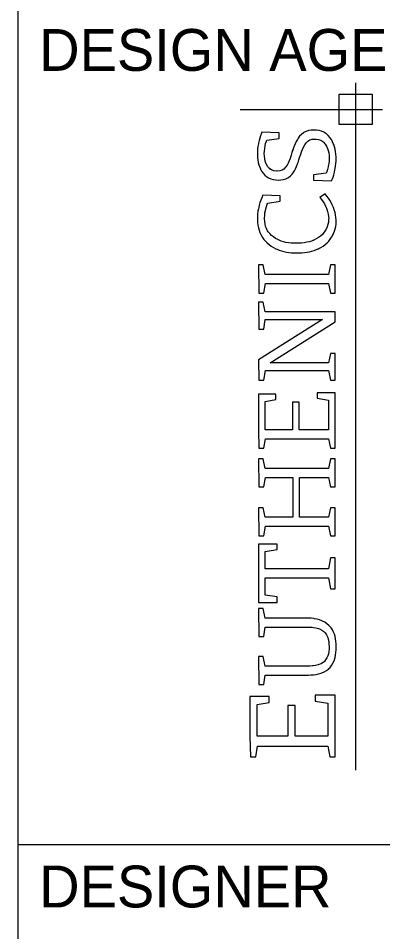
# Model space of a CAD drawing. Extents: x 0 to 34, y 0 to 22.
# Drawn here: x 32 to 32.871, y 2.292 to 4.476 of the extents above; entities that cross this region are included whole.
import ezdxf

# ---------------------------------------------------------------- set-up
doc = ezdxf.new("R2010")
doc.units = 0
for name, color, linetype in [('SH_Border', 7, 'Continuous'), ('SH_Data', 7, 'Continuous'), ('SH_Logo', 7, 'Continuous')]:
    doc.layers.add(name, color=color, linetype=linetype)

msp = doc.modelspace()

# ---------------------------------------------------------------- linework, layer by layer
at = {"layer": 'SH_Border'}
for p, q in [((32, 0.5), (32, 21.5)), ((32, 2.5), (33.5, 2.5))]:
    msp.add_line(p, q, dxfattribs=at)
at = {"layer": 'SH_Data'}
msp.add_line((32.75, 3.5), (32.75, 3.5), dxfattribs=at)
at = {"layer": 'SH_Logo'}
for p, q in [((32.8065, 2.6784), (32.8065, 4.3216)), ((32.5305, 4.258), (32.8702, 4.258))]:
    msp.add_line(p, q, dxfattribs=at)
for points in [[(32.767, 4.2214), (32.767, 4.2945), (32.846, 4.2945), (32.846, 4.2214)], [(32.6388, 4.1194), (32.6348, 4.1153), (32.6304, 4.1125), (32.6249, 4.1107), (32.6175, 4.11), (32.6107, 4.1109), (32.6052, 4.113), (32.6005, 4.1162), (32.5964, 4.1207), (32.5933, 4.1258), (32.5908, 4.1316), (32.5902, 4.134), (32.5889, 4.1399), (32.5882, 4.1459), (32.5879, 4.1522), (32.5882, 4.1584), (32.5888, 4.1644), (32.5898, 4.1705), (32.5911, 4.1762), (32.5929, 4.1821), (32.594, 4.1847), (32.6234, 4.1884), (32.6234, 4.2015), (32.5822, 4.2037), (32.581, 4.2007), (32.5788, 4.1949), (32.5769, 4.1891), (32.5753, 4.1833), (32.574, 4.1774), (32.5737, 4.1758), (32.5727, 4.1695), (32.572, 4.1635), (32.5715, 4.1574), (32.5714, 4.1516), (32.5714, 4.1494), (32.5718, 4.143), (32.5724, 4.1369), (32.5736, 4.1309), (32.575, 4.1252), (32.5769, 4.1198), (32.5787, 4.1156), (32.5816, 4.1102), (32.5851, 4.1052), (32.589, 4.101), (32.5935, 4.0973), (32.5981, 4.0942), (32.6033, 4.0919), (32.609, 4.0902), (32.6151, 4.0891), (32.6216, 4.0888), (32.6275, 4.0891), (32.6336, 4.0901), (32.6391, 4.0919), (32.644, 4.0943), (32.6458, 4.0954), (32.6506, 4.0991), (32.6548, 4.1034), (32.6584, 4.1083), (32.6599, 4.1107), (32.6627, 4.116), (32.6652, 4.1216), (32.6674, 4.1274), (32.6686, 4.131), (32.6706, 4.1369), (32.6724, 4.1426), (32.6742, 4.1485), (32.6749, 4.1508), (32.6769, 4.1567), (32.6791, 4.1623), (32.6816, 4.1676), (32.6844, 4.1728), (32.688, 4.1777), (32.6921, 4.1818), (32.6922, 4.1819), (32.697, 4.1848), (32.7026, 4.1865), (32.7092, 4.1871), (32.7115, 4.187), (32.7177, 4.186), (32.7231, 4.184), (32.7278, 4.1808), (32.7294, 4.1793), (32.7333, 4.175), (32.7366, 4.17), (32.7391, 4.1642), (32.7406, 4.1598), (32.742, 4.154), (32.7428, 4.1479), (32.7431, 4.141), (32.7428, 4.1344), (32.7421, 4.1283), (32.7409, 4.1222), (32.7406, 4.1203), (32.739, 4.1144), (32.737, 4.1086), (32.7355, 4.1052), (32.7054, 4.1011), (32.7054, 4.0883), (32.7486, 4.0867), (32.75, 4.0901), (32.7521, 4.0959), (32.7539, 4.1017), (32.7555, 4.1076), (32.7567, 4.1135), (32.7573, 4.1162), (32.7583, 4.1223), (32.759, 4.1283), (32.7595, 4.1343), (32.7596, 4.1403), (32.7596, 4.1447), (32.7591, 4.151), (32.7583, 4.1571), (32.7572, 4.1629), (32.7557, 4.1687), (32.7536, 4.1749), (32.7512, 4.1806), (32.7482, 4.1859), (32.7448, 4.1908), (32.7409, 4.1952), (32.7365, 4.1992), (32.7349, 4.2004), (32.7301, 4.2033), (32.7248, 4.2055), (32.719, 4.2071), (32.7129, 4.2081), (32.7063, 4.2084), (32.7, 4.2081), (32.6939, 4.2071), (32.6883, 4.2054), (32.6834, 4.2031), (32.6814, 4.2018), (32.6766, 4.198), (32.6723, 4.1938), (32.6687, 4.1889), (32.6671, 4.1863), (32.6642, 4.1811), (32.6616, 4.1755), (32.6592, 4.1698), (32.6579, 4.1661), (32.6541, 4.1546), (32.6524, 4.1487), (32.6497, 4.1405), (32.6474, 4.1349), (32.645, 4.1296), (32.6423, 4.1243)], [(32.7054, 4.1011), (32.7054, 4.0883), (32.7486, 4.0867), (32.75, 4.0901), (32.7521, 4.0959), (32.7539, 4.1017), (32.7555, 4.1076), (32.7567, 4.1135), (32.7573, 4.1162), (32.7583, 4.1223), (32.759, 4.1283), (32.7595, 4.1343), (32.7596, 4.1403), (32.7596, 4.1447), (32.7591, 4.151), (32.7583, 4.1571), (32.7572, 4.1629), (32.7557, 4.1687), (32.7539, 4.1742), (32.7536, 4.1749), (32.7512, 4.1806), (32.7482, 4.1859), (32.7448, 4.1908), (32.7409, 4.1952), (32.7365, 4.1992), (32.7349, 4.2004), (32.7301, 4.2033), (32.7248, 4.2055), (32.719, 4.2071), (32.7129, 4.2081), (32.7063, 4.2084), (32.7, 4.2081), (32.6939, 4.2071), (32.6883, 4.2054), (32.6834, 4.2031), (32.6814, 4.2018), (32.6766, 4.198), (32.6723, 4.1938), (32.6687, 4.1889), (32.6671, 4.1863), (32.6642, 4.1811), (32.6616, 4.1755), (32.6592, 4.1698), (32.6579, 4.1661), (32.656, 4.1603), (32.6541, 4.1546), (32.6524, 4.1487), (32.6516, 4.1464), (32.6497, 4.1405), (32.6474, 4.1349), (32.645, 4.1296), (32.6423, 4.1243), (32.6388, 4.1194), (32.6348, 4.1153), (32.6304, 4.1125), (32.6249, 4.1107), (32.6184, 4.1101), (32.6169, 4.1101), (32.6107, 4.1109), (32.6052, 4.113), (32.6006, 4.1161), (32.6003, 4.1164), (32.5964, 4.1207), (32.5933, 4.1258), (32.5908, 4.1316), (32.5902, 4.134), (32.5889, 4.1399), (32.5882, 4.1459), (32.5879, 4.1521), (32.5879, 4.1524), (32.5882, 4.1584), (32.5888, 4.1644), (32.5898, 4.1705), (32.5911, 4.1762), (32.5929, 4.1821), (32.594, 4.1847), (32.6234, 4.1884), (32.6234, 4.2015), (32.5822, 4.2037), (32.581, 4.2007), (32.5788, 4.1949), (32.5769, 4.1891), (32.5753, 4.1833), (32.574, 4.1774), (32.5737, 4.1758), (32.5727, 4.1695), (32.572, 4.1635), (32.5715, 4.1574), (32.5714, 4.1516), (32.5714, 4.1494), (32.5718, 4.143), (32.5724, 4.1369), (32.5736, 4.1309), (32.575, 4.1252), (32.5769, 4.1198), (32.5787, 4.1156), (32.5816, 4.1102), (32.5851, 4.1052), (32.589, 4.101), (32.5935, 4.0973), (32.5981, 4.0942), (32.6033, 4.0919), (32.609, 4.0902), (32.6151, 4.0891), (32.6216, 4.0888), (32.6275, 4.0891), (32.6336, 4.0901), (32.6391, 4.0919), (32.644, 4.0943), (32.6458, 4.0954), (32.6506, 4.0991), (32.6548, 4.1034), (32.6584, 4.1083), (32.6599, 4.1107), (32.6627, 4.116), (32.6652, 4.1216), (32.6674, 4.1274), (32.6686, 4.131), (32.6706, 4.1369), (32.6724, 4.1426), (32.6742, 4.1485), (32.6749, 4.1508), (32.6769, 4.1567), (32.6791, 4.1623), (32.6816, 4.1676), (32.6844, 4.1728), (32.688, 4.1777), (32.6921, 4.1818), (32.6922, 4.1819), (32.697, 4.1848), (32.7026, 4.1865), (32.7092, 4.1871), (32.7115, 4.187), (32.7177, 4.186), (32.7231, 4.184), (32.7278, 4.1808), (32.7294, 4.1793), (32.7333, 4.175), (32.7366, 4.17), (32.7391, 4.1642), (32.7406, 4.1598), (32.742, 4.154), (32.7428, 4.1479), (32.7431, 4.1416), (32.7431, 4.1403), (32.7428, 4.1344), (32.7421, 4.1283), (32.7409, 4.1222), (32.7406, 4.1203), (32.739, 4.1144), (32.737, 4.1086), (32.7355, 4.1052)], [(32.587, 3.9472), (32.5908, 3.9428), (32.5949, 3.9386), (32.5995, 3.9347), (32.6044, 3.9311), (32.6097, 3.9279), (32.6153, 3.9249), (32.6186, 3.9234), (32.6237, 3.9213), (32.6291, 3.9196), (32.6348, 3.9181), (32.6406, 3.9168), (32.6467, 3.9158), (32.653, 3.9152), (32.6595, 3.9148), (32.6663, 3.9146), (32.6709, 3.9147), (32.6776, 3.915), (32.684, 3.9156), (32.6902, 3.9165), (32.6961, 3.9176), (32.7018, 3.919), (32.7072, 3.9207), (32.7124, 3.9226), (32.7173, 3.9249), (32.7174, 3.9249), (32.7231, 3.9279), (32.7284, 3.9312), (32.7333, 3.9348), (32.7378, 3.9387), (32.7419, 3.9429), (32.7456, 3.9474), (32.7488, 3.9522), (32.751, 3.9558), (32.7536, 3.9612), (32.7558, 3.9668), (32.7574, 3.9725), (32.7586, 3.9783), (32.7594, 3.9843), (32.7596, 3.9906), (32.7596, 3.9937), (32.7591, 3.9995), (32.7583, 4.0055), (32.757, 4.0114), (32.7552, 4.0174), (32.7531, 4.0234), (32.7525, 4.0248), (32.7502, 4.0301), (32.7475, 4.0354), (32.7446, 4.0406), (32.7412, 4.0457), (32.7374, 4.0507), (32.7333, 4.0557), (32.7205, 4.047), (32.7244, 4.0422), (32.7282, 4.0371), (32.7314, 4.032), (32.7342, 4.0268), (32.7365, 4.0216), (32.7372, 4.0197), (32.7392, 4.0135), (32.7406, 4.0076), (32.7415, 4.0017), (32.7418, 3.9961), (32.7417, 3.9945), (32.7412, 3.9884), (32.7401, 3.9825), (32.7382, 3.9769), (32.7357, 3.9715), (32.7326, 3.9664), (32.7304, 3.9633), (32.7266, 3.959), (32.7223, 3.9551), (32.7175, 3.9515), (32.7121, 3.9482), (32.7063, 3.9453), (32.7054, 3.945), (32.7004, 3.9431), (32.695, 3.9415), (32.6893, 3.9401), (32.6834, 3.9391), (32.6771, 3.9383), (32.6706, 3.9379), (32.6636, 3.9377), (32.6583, 3.9378), (32.6518, 3.9383), (32.6456, 3.939), (32.6396, 3.94), (32.6339, 3.9414), (32.6285, 3.9431), (32.6234, 3.9451), (32.6202, 3.9466), (32.6147, 3.9495), (32.6096, 3.9529), (32.605, 3.9567), (32.601, 3.9608), (32.5974, 3.9653), (32.5959, 3.9677), (32.5933, 3.9728), (32.5911, 3.9782), (32.5897, 3.984), (32.5888, 3.9902), (32.5885, 3.9966), (32.5885, 3.9982), (32.5888, 4.0041), (32.5895, 4.0102), (32.5906, 4.0165), (32.5914, 4.0202), (32.5931, 4.026), (32.5951, 4.0317), (32.596, 4.034), (32.6258, 4.0384), (32.6258, 4.0513), (32.5845, 4.0531), (32.5843, 4.0525), (32.5818, 4.0466), (32.5795, 4.0407), (32.5776, 4.0349), (32.5759, 4.0292), (32.5746, 4.0237), (32.5739, 4.0204), (32.5727, 4.0143), (32.572, 4.0082), (32.5715, 4.0022), (32.5714, 3.9963), (32.5715, 3.9934), (32.5718, 3.9871), (32.5726, 3.981), (32.5738, 3.9751), (32.5754, 3.9694), (32.5775, 3.9638), (32.5799, 3.9586), (32.5827, 3.9535), (32.5836, 3.952)], [(32.6518, 3.9383), (32.6456, 3.939), (32.6396, 3.94), (32.6339, 3.9414), (32.6285, 3.9431), (32.6234, 3.9451), (32.6202, 3.9466), (32.6147, 3.9495), (32.6096, 3.9529), (32.605, 3.9567), (32.601, 3.9608), (32.5974, 3.9653), (32.5959, 3.9677), (32.5933, 3.9728), (32.5911, 3.9782), (32.5897, 3.984), (32.5888, 3.9902), (32.5885, 3.9966), (32.5885, 3.9982), (32.5888, 4.0041), (32.5895, 4.0102), (32.5906, 4.0165), (32.5914, 4.0202), (32.5931, 4.026), (32.5951, 4.0317), (32.596, 4.034), (32.6258, 4.0384), (32.6258, 4.0513), (32.5846, 4.0531), (32.5818, 4.0466), (32.5795, 4.0407), (32.5776, 4.0349), (32.5759, 4.0292), (32.5746, 4.0237), (32.5739, 4.0204), (32.5727, 4.0143), (32.572, 4.0082), (32.5715, 4.0022), (32.5714, 3.9963), (32.5715, 3.9934), (32.5718, 3.9871), (32.5726, 3.981), (32.5738, 3.9751), (32.5754, 3.9694), (32.5775, 3.9638), (32.5799, 3.9586), (32.5827, 3.9535), (32.5836, 3.952), (32.587, 3.9472), (32.5908, 3.9428), (32.5949, 3.9386), (32.5995, 3.9347), (32.6044, 3.9311), (32.6097, 3.9279), (32.6153, 3.9249), (32.6186, 3.9234), (32.6237, 3.9213), (32.6291, 3.9196), (32.6348, 3.9181), (32.6406, 3.9168), (32.6467, 3.9158), (32.653, 3.9152), (32.6595, 3.9148), (32.6663, 3.9146), (32.6709, 3.9147), (32.6776, 3.915), (32.684, 3.9156), (32.6902, 3.9165), (32.6961, 3.9176), (32.7018, 3.919), (32.7072, 3.9207), (32.7124, 3.9226), (32.7179, 3.9252), (32.7231, 3.9279), (32.7284, 3.9312), (32.7333, 3.9348), (32.7378, 3.9387), (32.7419, 3.9429), (32.7456, 3.9474), (32.7488, 3.9522), (32.751, 3.9558), (32.7536, 3.9612), (32.7558, 3.9668), (32.7574, 3.9725), (32.7586, 3.9783), (32.7594, 3.9843), (32.7596, 3.9906), (32.7596, 3.9937), (32.7591, 3.9995), (32.7583, 4.0055), (32.757, 4.0114), (32.7552, 4.0174), (32.7531, 4.0234), (32.7525, 4.0248), (32.7502, 4.0301), (32.7475, 4.0354), (32.7446, 4.0406), (32.7412, 4.0457), (32.7374, 4.0507), (32.7333, 4.0557), (32.7205, 4.047), (32.7244, 4.0422), (32.7282, 4.0371), (32.7314, 4.032), (32.7342, 4.0268), (32.7365, 4.0216), (32.7372, 4.0197), (32.7392, 4.0135), (32.7406, 4.0076), (32.7415, 4.0017), (32.7418, 3.9961), (32.7417, 3.9945), (32.7412, 3.9884), (32.7401, 3.9825), (32.7382, 3.9769), (32.7357, 3.9715), (32.7326, 3.9664), (32.7304, 3.9633), (32.7266, 3.959), (32.7223, 3.9551), (32.7175, 3.9515), (32.7121, 3.9482), (32.706, 3.9452), (32.7004, 3.9431), (32.695, 3.9415), (32.6893, 3.9401), (32.6834, 3.9391), (32.6771, 3.9383), (32.6706, 3.9379), (32.6636, 3.9377), (32.6583, 3.9378)], [(32.5737, 3.886), (32.5751, 3.8189), (32.5864, 3.8189), (32.5905, 3.8416), (32.7413, 3.8416), (32.746, 3.8189), (32.7573, 3.8189), (32.7573, 3.886), (32.746, 3.886), (32.7413, 3.8631), (32.5902, 3.8631), (32.5851, 3.886)], [(32.5902, 3.8631), (32.5851, 3.886), (32.5737, 3.886), (32.5751, 3.8189), (32.5864, 3.8189), (32.5905, 3.8416), (32.7413, 3.8416), (32.746, 3.8189), (32.7573, 3.8189), (32.7573, 3.886), (32.746, 3.886), (32.7413, 3.8631)], [(32.5904, 3.6335), (32.7412, 3.6335), (32.746, 3.6109), (32.7573, 3.6109), (32.7573, 3.6745), (32.746, 3.6745), (32.7412, 3.6519), (32.6016, 3.6519), (32.7573, 3.7496), (32.7573, 3.7738), (32.5903, 3.7738), (32.5851, 3.7967), (32.5737, 3.7967), (32.5751, 3.7328), (32.5864, 3.7328), (32.5902, 3.7556), (32.7267, 3.7556), (32.5737, 3.6593), (32.5751, 3.6109), (32.5864, 3.6109)], [(32.6016, 3.6519), (32.7573, 3.7496), (32.7573, 3.7738), (32.5903, 3.7738), (32.5851, 3.7967), (32.5737, 3.7967), (32.5751, 3.7328), (32.5864, 3.7328), (32.5902, 3.7556), (32.7267, 3.7556), (32.5737, 3.6593), (32.5751, 3.6109), (32.5864, 3.6109), (32.5904, 3.6335), (32.7412, 3.6335), (32.746, 3.6109), (32.7573, 3.6109), (32.7573, 3.6745), (32.746, 3.6745), (32.7412, 3.6519)], [(32.7142, 3.5804), (32.7142, 3.5673), (32.7412, 3.5631), (32.7412, 3.4918), (32.6713, 3.4918), (32.6713, 3.5581), (32.6555, 3.5581), (32.6555, 3.4918), (32.5898, 3.4918), (32.5898, 3.5599), (32.6153, 3.5641), (32.6153, 3.5773), (32.5737, 3.5773), (32.5737, 3.4916), (32.5751, 3.4478), (32.5864, 3.4478), (32.5905, 3.4703), (32.7412, 3.4703), (32.746, 3.4478), (32.7573, 3.4478), (32.7573, 3.5804)], [(32.6555, 3.5581), (32.6555, 3.4918), (32.5898, 3.4918), (32.5898, 3.5599), (32.6153, 3.5641), (32.6153, 3.5773), (32.5737, 3.5773), (32.5737, 3.4916), (32.5751, 3.4478), (32.5864, 3.4478), (32.5905, 3.4703), (32.7412, 3.4703), (32.746, 3.4478), (32.7573, 3.4478), (32.7573, 3.5804), (32.7142, 3.5804), (32.7142, 3.5673), (32.7412, 3.5631), (32.7412, 3.4918), (32.6713, 3.4918), (32.6713, 3.5581)], [(32.5737, 3.4222), (32.5751, 3.3553), (32.5864, 3.3553), (32.5904, 3.3778), (32.6558, 3.3778), (32.6558, 3.2828), (32.5903, 3.2828), (32.5851, 3.3056), (32.5737, 3.3056), (32.5751, 3.2386), (32.5864, 3.2386), (32.5904, 3.2612), (32.7412, 3.2612), (32.746, 3.2386), (32.7573, 3.2386), (32.7573, 3.3056), (32.746, 3.3056), (32.7412, 3.2828), (32.6719, 3.2828), (32.6719, 3.3778), (32.7412, 3.3778), (32.746, 3.3553), (32.7573, 3.3553), (32.7573, 3.4222), (32.746, 3.4222), (32.7412, 3.3994), (32.5903, 3.3994), (32.5851, 3.4222)], [(32.5903, 3.3994), (32.5851, 3.4222), (32.5737, 3.4222), (32.5751, 3.3553), (32.5864, 3.3553), (32.5904, 3.3778), (32.6558, 3.3778), (32.6558, 3.2828), (32.5903, 3.2828), (32.5851, 3.3056), (32.5737, 3.3056), (32.5751, 3.2386), (32.5864, 3.2386), (32.5904, 3.2612), (32.7412, 3.2612), (32.746, 3.2386), (32.7573, 3.2386), (32.7573, 3.3056), (32.746, 3.3056), (32.7412, 3.2828), (32.6719, 3.2828), (32.6719, 3.3778), (32.7412, 3.3778), (32.746, 3.3553), (32.7573, 3.3553), (32.7573, 3.4222), (32.746, 3.4222), (32.7412, 3.3994)], [(32.5898, 3.1595), (32.5898, 3.2008), (32.6187, 3.2055), (32.6187, 3.2186), (32.5737, 3.2186), (32.5737, 3.0791), (32.6187, 3.0791), (32.6187, 3.0922), (32.5898, 3.0968), (32.5898, 3.1382), (32.7412, 3.1382), (32.746, 3.1119), (32.7573, 3.1119), (32.7573, 3.1858), (32.746, 3.1858), (32.7412, 3.1595)], [(32.5898, 3.1595), (32.5898, 3.2008), (32.6187, 3.2055), (32.6187, 3.2186), (32.5737, 3.2186), (32.5737, 3.0791), (32.6187, 3.0791), (32.6187, 3.0922), (32.5898, 3.0968), (32.5898, 3.1382), (32.7412, 3.1382), (32.746, 3.1119), (32.7573, 3.1119), (32.7573, 3.1858), (32.746, 3.1858), (32.7412, 3.1595)], [(32.7428, 2.973), (32.7427, 2.9683), (32.7421, 2.9618), (32.741, 2.9561), (32.7394, 2.9512), (32.7376, 2.9469), (32.7345, 2.9417), (32.7307, 2.9375), (32.7292, 2.9361), (32.7242, 2.9327), (32.7186, 2.9304), (32.7164, 2.9297), (32.7105, 2.9283), (32.7045, 2.9276), (32.7029, 2.9274), (32.6967, 2.9271), (32.6908, 2.927), (32.5902, 2.927), (32.5851, 2.9498), (32.5737, 2.9498), (32.5751, 2.8829), (32.5864, 2.8829), (32.5903, 2.9054), (32.6908, 2.9054), (32.6932, 2.9055), (32.6991, 2.9057), (32.7057, 2.9063), (32.7116, 2.907), (32.7175, 2.9083), (32.7236, 2.9099), (32.7257, 2.9106), (32.7311, 2.913), (32.7363, 2.9161), (32.7412, 2.9199), (32.7413, 2.92), (32.7453, 2.9239), (32.7488, 2.9285), (32.752, 2.9338), (32.7546, 2.9399), (32.7555, 2.9422), (32.757, 2.9474), (32.7581, 2.953), (32.7589, 2.9591), (32.7595, 2.9657), (32.7596, 2.9727), (32.7596, 2.973), (32.7595, 2.9798), (32.7589, 2.9862), (32.7581, 2.9922), (32.7569, 2.9978), (32.7555, 3.0029), (32.7536, 3.0078), (32.7507, 3.0134), (32.7475, 3.0183), (32.7438, 3.0226), (32.7422, 3.0242), (32.7376, 3.0283), (32.7326, 3.0317), (32.7273, 3.0345), (32.7254, 3.0353), (32.7197, 3.0374), (32.7139, 3.039), (32.7079, 3.0403), (32.7061, 3.0405), (32.6999, 3.0412), (32.6938, 3.0416), (32.6879, 3.0418), (32.5902, 3.0418), (32.5851, 3.0647), (32.5737, 3.0647), (32.5751, 2.9977), (32.5864, 2.9977), (32.5902, 3.0203), (32.6879, 3.0203), (32.6901, 3.0203), (32.6962, 3.0201), (32.7023, 3.0197), (32.7052, 3.0195), (32.7112, 3.0184), (32.7171, 3.0169), (32.7199, 3.0158), (32.7253, 3.0131), (32.7302, 3.0095), (32.7333, 3.0063), (32.7366, 3.0013), (32.7394, 2.9956), (32.7406, 2.9917), (32.7418, 2.9861), (32.7425, 2.9798)], [(32.5902, 2.927), (32.5851, 2.9498), (32.5737, 2.9498), (32.5751, 2.8829), (32.5864, 2.8829), (32.5903, 2.9054), (32.6908, 2.9054), (32.6932, 2.9055), (32.6991, 2.9057), (32.7057, 2.9063), (32.7116, 2.907), (32.7175, 2.9083), (32.7236, 2.9099), (32.7257, 2.9106), (32.7311, 2.913), (32.7363, 2.9161), (32.7412, 2.9199), (32.7453, 2.9239), (32.7488, 2.9285), (32.752, 2.9338), (32.7546, 2.9399), (32.7555, 2.9422), (32.757, 2.9474), (32.7581, 2.953), (32.7589, 2.9591), (32.7595, 2.9657), (32.7596, 2.9727), (32.7596, 2.973), (32.7595, 2.9798), (32.7589, 2.9862), (32.7581, 2.9922), (32.7569, 2.9978), (32.7555, 3.0029), (32.7536, 3.0078), (32.7507, 3.0134), (32.7475, 3.0183), (32.7438, 3.0226), (32.7422, 3.0242), (32.7376, 3.0283), (32.7326, 3.0317), (32.7273, 3.0345), (32.7254, 3.0353), (32.7197, 3.0374), (32.7139, 3.039), (32.7079, 3.0403), (32.7061, 3.0405), (32.6999, 3.0412), (32.6938, 3.0416), (32.6879, 3.0418), (32.5902, 3.0418), (32.5851, 3.0647), (32.5737, 3.0647), (32.5751, 2.9977), (32.5864, 2.9977), (32.5902, 3.0203), (32.6901, 3.0203), (32.6962, 3.0201), (32.7023, 3.0197), (32.7052, 3.0195), (32.7112, 3.0184), (32.7171, 3.0169), (32.7199, 3.0158), (32.7253, 3.0131), (32.7302, 3.0095), (32.7333, 3.0063), (32.7366, 3.0013), (32.7394, 2.9956), (32.7406, 2.9917), (32.7418, 2.9861), (32.7425, 2.9798), (32.7428, 2.973), (32.7427, 2.9683), (32.7421, 2.9618), (32.741, 2.9561), (32.7394, 2.9512), (32.7376, 2.9469), (32.7345, 2.9417), (32.7307, 2.9375), (32.7292, 2.9361), (32.7242, 2.9327), (32.7186, 2.9304), (32.7164, 2.9297), (32.7105, 2.9283), (32.7034, 2.9274), (32.6967, 2.9271), (32.6908, 2.927)], [(32.5674, 2.7102), (32.5719, 2.7353), (32.7394, 2.7353), (32.7447, 2.7102), (32.7573, 2.7102), (32.7573, 2.8576), (32.7094, 2.8576), (32.7094, 2.843), (32.7395, 2.8385), (32.7395, 2.7593), (32.6618, 2.7593), (32.6618, 2.8328), (32.6442, 2.8328), (32.6442, 2.7593), (32.5712, 2.7593), (32.5712, 2.8349), (32.5995, 2.8396), (32.5995, 2.8541), (32.5533, 2.8541), (32.5533, 2.7589), (32.5549, 2.7102)], [(32.5712, 2.7593), (32.5712, 2.8349), (32.5995, 2.8396), (32.5995, 2.8541), (32.5533, 2.8541), (32.5533, 2.7589), (32.5549, 2.7102), (32.5674, 2.7102), (32.5719, 2.7353), (32.7394, 2.7353), (32.7447, 2.7102), (32.7573, 2.7102), (32.7573, 2.8576), (32.7094, 2.8576), (32.7094, 2.843), (32.7395, 2.8385), (32.7395, 2.7593), (32.6618, 2.7593), (32.6618, 2.8328), (32.6442, 2.8328), (32.6442, 2.7593)]]:
    msp.add_lwpolyline(points, close=True, dxfattribs=at)
for points in [[(32.5898, 3.2008), (32.6187, 3.2055), (32.6187, 3.2186), (32.5737, 3.2186)], [(32.5898, 3.1382), (32.7412, 3.1382), (32.746, 3.1119), (32.7573, 3.1119), (32.7573, 3.1858), (32.746, 3.1858), (32.7412, 3.1595), (32.5898, 3.1595)]]:
    msp.add_lwpolyline(points, dxfattribs=at)

# ---------------------------------------------------------------- texts
at = {"layer": 'SH_Data'}
for s, p in [('DESIGN AGENCY', (32.05, 4.35)), ('DESIGNER', (32.05, 2.35))]:
    msp.add_text(s, height=0.1, dxfattribs=at).set_placement(p)

doc.saveas('drawing.dxf')
